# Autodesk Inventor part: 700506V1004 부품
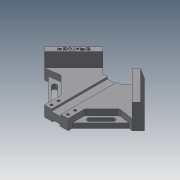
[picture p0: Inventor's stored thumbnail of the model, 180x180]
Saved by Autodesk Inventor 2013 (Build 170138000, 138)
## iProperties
Created: 2020-05
Part Number: 700506V1004 부품
Material: Generic
Document SubType Name: Modeling
Designer: user
Density: 1 g/cm^3
Author: user
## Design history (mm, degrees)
sketch "스케치1"
  geometry: L1 (35.355, -49.497)-(84.853, 0); L2 (84.853, 0)-(20, 64.853); L3 (35.355, -49.497)-(16.005, -30.147); L4 (16.005, -30.147)-(-16.005, -30.147); L5 (-16.005, -30.147)-(-35.355, -49.497); L6 (-35.355, -49.497)-(-84.853, 0); L7 (-84.853, 0)-(-20, 64.853); L8 (20, 64.853)-(-20, 64.853); 3 further points
  constraints: 16 end point, 4 parallel, 2 midpoint, 2 perpendicular, 2 vertical alignment, 1 horizontal
  dimensions: "d0" = 120 distance between parallel lines of L7 L1; "d2" = 120 distance between parallel lines of L6 L2; "d3" = 50 distance between parallel lines of L6 L3; "d4" = 40 distance of L2.end L7.end; "d5" = 95 distance between parallel lines of L8 L4; "d7" = 50 distance between parallel lines of L5 L1; "d9" = 0 vertical distance of L1.end point (0, 0)
extrude "돌출1" new body sketch "스케치1" distance "d10" = 18; taper "d11" = 0 deg
sketch "스케치2"
  geometry: L1 (-35.355, 49.497)-(-84.853, 0) reference; L2 (-84.853, 0)-(-20, -64.853) reference; L3 (84.853, 0)-(35.355, 49.497) reference; L4 (-35.355, 49.497)-(-84.853, 0); L5 (-84.853, 0)-(-74.246, -10.607); L6 (-74.246, -10.607)-(-24.749, 38.891); L7 (-24.749, 38.891)-(-35.355, 49.497); L8 (35.355, 49.497)-(84.853, 0); L9 (84.853, 0)-(74.246, -10.607); L10 (74.246, -10.607)-(24.749, 38.891); L11 (24.749, 38.891)-(35.355, 49.497); 1 further point
  constraints: 16 end point, 5 equal length, 3 perpendicular
  dimensions: "d12" = 15 distance of L5.end L1.end; "d13" = 15 distance of L3.start L9.end
extrude "돌출2" join sketch "스케치2" distance "d14" = 24; taper "d15" = 0 deg
sketch "스케치3"
  geometry: L1 (-74.246, -10.607)-(-20, -64.853) reference; L2 (-74.246, -10.607)-(-49.497, -7.071); L3 (-49.497, -7.071)-(-20, -36.569); L4 (-20, -36.569)-(-20, -64.853); L5 (-35.355, 49.497)-(-84.853, 0) reference; L6 (-35.355, 49.497)-(-84.853, 0) reference; L7 (-84.853, 0)-(-74.246, -10.607) reference; L8 (-74.246, -10.607)-(-24.749, 38.891) reference; L9 (-24.749, 38.891)-(-35.355, 49.497) reference; L10 (-74.246, -10.607)-(-20, -64.853); 1 further point
  constraints: 8 end point, 1 collinear, 1 parallel, 1 vertical
  dimensions: "d16" = 20 distance between parallel lines of L1 L3; "d17" = 30 distance from line of L2.end L5
extrude "돌출3" cut sketch "스케치3" distance "d18" = 10; taper "d19" = 0 deg
sketch "스케치4"
  geometry: L1 (-20, -64.853)-(-74.246, -10.607) reference; L2 (-20, -36.569)-(-20, -64.853) reference; L3 (-49.497, -7.071)-(-20, -36.569) reference; L4 (-74.246, -10.607)-(-49.497, -7.071) reference; L5 (-74.246, -10.607)-(-68.059, -9.723); L6 (-68.059, -9.723)-(-20, -57.782); L7 (-20, -64.853)-(-20, -57.782); L8 (-20, -57.782)-(-20, -64.853); L9 (-74.246, -10.607)-(-20, -64.853); 1 further point
  constraints: 10 end point, 3 collinear, 2 point on line, 1 parallel
  dimensions: "d20" = 5 distance between parallel lines of L6 L1
extrude "돌출4" cut sketch "스케치4" stored distance "d21" = 10; taper "d22" = 0 deg
sketch "스케치5"
  geometry: L1 (-35.355, 49.497)-(-84.853, 0) reference; L2 (-84.853, 0)-(-74.246, -10.607) reference; L3 (-74.246, -10.607)-(-24.749, 38.891) reference; L4 (-24.749, 38.891)-(-35.355, 49.497) reference; L5 (-52.326, -21.213)-(-32.527, -41.012); L6 (-26.87, -35.355)-(-46.669, -15.556); A1 r 4 centre (-49.497, -18.385) between (-52.326, -21.213) and (-46.669, -15.556); A2 r 4 centre (-29.698, -38.184) between (-32.527, -41.012) and (-26.87, -35.355); 1 further point
  constraints: 4 end point, 4 point on circle, 2 centre point, 2 parallel
  dimensions: "d23" = 8 diameter of A1; "d24" = 8 diameter of A2; "d25" = 12 distance from line of L2 A1.centre; "d26" = 12 distance from line of L2 A2.centre; "d27" = 28 distance of A2.centre A1.centre; "d28" = 38 distance from line of A1.centre L1; "d29" = 8 distance between parallel lines of L6 L5; "d30" = 16 distance between parallel lines of L2 L6
extrude "돌출5" cut sketch "스케치5" stored distance "d31" = 10; taper "d32" = 0 deg
chamfer "모따기1" distance "d33" = 5; stored, may be unused: second distance "d34" = 15, angle "d35" = 45 deg
chamfer "모따기2" distance "d36" = 5; stored, may be unused: second distance "d37" = 15, angle "d38" = 45 deg
sketch "스케치7"
  geometry: L1 (-20, -64.853)-(20, -64.853) reference; L2 (16.005, 30.147)-(-16.005, 30.147) reference; L3 (-8, 30.147)-(8, 30.147); L4 (8, 30.147)-(8, -64.853); L5 (8, -64.853)-(-8, -64.853); L6 (-8, -64.853)-(-8, 30.147); 2 further points
  constraints: 8 end point, 2 midpoint, 2 parallel, 1 horizontal, 1 perpendicular, 1 point on line
  dimensions: "d39" = 16 distance between parallel lines of L6 L4
extrude "돌출6" cut sketch "스케치7" distance "d41" = 3.5; taper "d42" = 0 deg
sketch "스케치8"
  geometry: L1 (16.005, -30.147)-(-16.005, -30.147) reference; L2 (-20, 64.853)-(20, 64.853) reference; L3 (-6, 64.853)-(6, 64.853); L4 (6, 64.853)-(6, -30.147); L5 (6, -30.147)-(-6, -30.147); L6 (-6, -30.147)-(-6, 64.853); 2 further points
  constraints: 8 end point, 2 parallel, 2 point on line, 1 horizontal, 1 midpoint, 1 perpendicular, 1 vertical alignment
  dimensions: "d43" = 12 distance between parallel lines of L4 L6
extrude "돌출7" cut sketch "스케치8" distance "d45" = 3; taper "d46" = 0 deg
sketch "스케치10"
  geometry: L1 (-20, 64.853)-(-6, 64.853) reference; L2 (6, 64.853)-(6, -30.147) reference; L3 (16.005, -30.147)-(6, -30.147) reference; L4 (35.355, -49.497)-(16.005, -30.147) reference; L5 (84.853, 0)-(35.355, -49.497) reference; L6 (20, 64.853)-(84.853, 0) reference; L7 (6, 64.853)-(20, 64.853) reference; L8 (6, 64.853)-(6, -30.147) reference; L9 (-6, 64.853)-(6, 64.853) reference; L10 (-6, -30.147)-(-6, 64.853) reference; L11 (6, -30.147)-(-6, -30.147) reference; 5 further points
  constraints: 2 horizontal alignment, 2 vertical alignment
  dimensions: "d47" = 6 distance from line of L1 point (-14, 58.853); "d48" = 12 distance of point (-14, 58.853) point (-14, 46.853); "d49" = 14 horizontal distance of point (-14, 58.853) point (0, 0); "d50" = 14 horizontal distance of point (14, 58.853) point (0, 0)
hole "구멍1" sketch "스케치10" at (-14, 58.853), (-14, 46.853), (14, 58.853), (14, 46.853) diameter "d51" = 4.5; stored, may be unused: countersink angle "d55" = 90 deg, drill point angle "d57" = 118 deg; dims "d52" = 6, "d53" = 8, "d54" = 10, "d56" = 8
fillet "모깎기1" dims "d58" = 5
fillet "모깎기2" dims "d59" = 5
sketch "스케치11"
  geometry: L1 (-74.246, -10.607)-(-24.749, 38.891) reference; L2 (-24.749, 38.891)-(-31.82, 45.962) reference; 2 further points
  constraints: 1 other
  dimensions: "d60" = 35 distance from line of L2 point (-53.033, 17.678); "d61" = 5 distance from line of L1 point (-53.033, 17.678)
feature "엠보싱1" sketch "스케치11" dims "d0" = 120, "d2" = 120, "d3" = 50, "d4" = 40, "d5" = 95, "d7" = 50, "d9" = 0, "d13" = 15, "d62" = 0.5, "d63" = 0
node "솔리드1"
mirror "대칭1"
node "투영된 루프1"
node "투영된 루프2"
node "투영된 루프3"
node "투영된 루프4"
